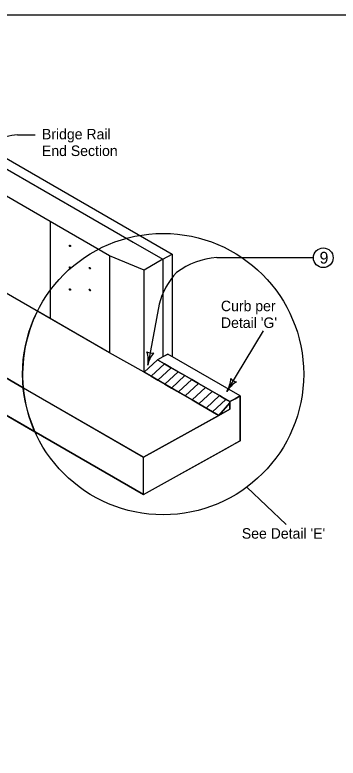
# Model space of a CAD drawing. Extents: x -2134934 to -2124557, y -2139046 to -2134021.
# Drawn here: x -2125788 to -2125295, y -2138168 to -2137036 of the extents above; entities that cross this region are included whole.
import ezdxf

# ---------------------------------------------------------------- set-up
doc = ezdxf.new("R2010")
doc.units = 0
for name, color, linetype in [('Barrier', 7, 'Continuous'), ('BridgeSuperStructureExisting', 7, 'Continuous'), ('dsnAlignmentStation', 7, 'Continuous'), ('dsnCellElements', 7, 'Continuous')]:
    doc.layers.add(name, color=color, linetype=linetype)

msp = doc.modelspace()

# ---------------------------------------------------------------- linework, layer by layer
at = {"layer": 'BridgeSuperStructureExisting'}
for p, q in [((-2126050, -2137110.4), (-2125548.2, -2137400.1)), ((-2125783.6, -2137218.5), (-2125756.7, -2137218.5)), ((-2125753.4, -2137487.2), (-2126112.2, -2137280.1)), ((-2125643.5, -2137550.7), (-2126112.2, -2137280.1)), ((-2125775, -2137603.9), (-2126226.3, -2137343.3)), ((-2126226.3, -2137343.3), (-2125775, -2137603.9)), ((-2125734, -2137350.5), (-2125734, -2137498.4)), ((-2126226.3, -2137400), (-2125757.2, -2137670.8)), ((-2125562.4, -2137408.2), (-2125548.2, -2137400.1)), ((-2125548.2, -2137400.1), (-2125548.2, -2137556.2)), ((-2125643.5, -2137402.8), (-2125643.5, -2137550.7)), ((-2125480.2, -2137405.5), (-2125332.7, -2137405.5)), ((-2125590.7, -2137580.2), (-2125590.7, -2137424.6)), ((-2126029.2, -2137457.2), (-2125591.9, -2137709.6)), ((-2125568, -2137476.6), (-2125585.2, -2137569.6)), ((-2125734, -2137498.4), (-2125753.4, -2137487.2)), ((-2125643.5, -2137550.7), (-2125734, -2137498.4)), ((-2126029.2, -2137513.8), (-2125591.9, -2137766.2)), ((-2125591.9, -2137766.2), (-2126029.2, -2137513.8)), ((-2125464.8, -2137609.5), (-2125408.7, -2137517.1)), ((-2125590.7, -2137580.2), (-2125643.5, -2137550.7)), ((-2125590.7, -2137580.2), (-2125643.5, -2137550.7)), ((-2125562.4, -2137556.9), (-2125570.2, -2137561.3)), ((-2125444.3, -2137616.2), (-2125554.5, -2137552.6)), ((-2125444.3, -2137616.2), (-2125554.5, -2137552.6)), ((-2125570.2, -2137561.3), (-2125590.7, -2137580.2)), ((-2125570.2, -2137561.3), (-2125590.7, -2137580.2)), ((-2125580.2, -2137586.3), (-2125559.8, -2137567.3)), ((-2125559.8, -2137567.3), (-2125580.2, -2137586.3)), ((-2125559.8, -2137567.3), (-2125580.2, -2137586.3)), ((-2125559.8, -2137567.3), (-2125570.2, -2137561.3)), ((-2125570.2, -2137561.3), (-2125559.8, -2137567.3)), ((-2125460, -2137624.9), (-2125570.2, -2137561.3)), ((-2125549.4, -2137573.3), (-2125559.8, -2137567.3)), ((-2125559.8, -2137567.3), (-2125549.4, -2137573.3)), ((-2125580.2, -2137586.3), (-2125590.7, -2137580.2)), ((-2125590.7, -2137580.2), (-2125580.2, -2137586.3)), ((-2125480.5, -2137643.9), (-2125590.7, -2137580.2)), ((-2125476.9, -2137645.9), (-2125590.7, -2137580.2)), ((-2125569.8, -2137592.3), (-2125549.4, -2137573.3)), ((-2125549.4, -2137573.3), (-2125569.8, -2137592.3)), ((-2125549.4, -2137573.3), (-2125569.8, -2137592.3)), ((-2125559.4, -2137598.3), (-2125539, -2137579.3)), ((-2125539, -2137579.3), (-2125559.4, -2137598.3)), ((-2125539, -2137579.3), (-2125559.4, -2137598.3)), ((-2125539, -2137579.3), (-2125549.4, -2137573.3)), ((-2125549.4, -2137573.3), (-2125539, -2137579.3)), ((-2125528.6, -2137585.3), (-2125539, -2137579.3)), ((-2125539, -2137579.3), (-2125528.6, -2137585.3)), ((-2125580.2, -2137586.3), (-2125569.8, -2137592.3)), ((-2125569.8, -2137592.3), (-2125559.4, -2137598.3)), ((-2125549, -2137604.3), (-2125528.6, -2137585.3)), ((-2125528.6, -2137585.3), (-2125549, -2137604.3)), ((-2125528.6, -2137585.3), (-2125549, -2137604.3)), ((-2125518.3, -2137591.3), (-2125538.4, -2137609.9)), ((-2125775, -2137603.9), (-2125591.9, -2137709.6)), ((-2125591.9, -2137709.6), (-2125775, -2137603.9)), ((-2125559.4, -2137598.3), (-2125549, -2137604.3)), ((-2125549, -2137604.3), (-2125528.2, -2137616.3)), ((-2125528.2, -2137616.3), (-2125507.8, -2137597.3)), ((-2125507.8, -2137597.3), (-2125528.2, -2137616.3)), ((-2125507.8, -2137597.3), (-2125528.2, -2137616.3)), ((-2125517.8, -2137622.3), (-2125497.4, -2137603.3)), ((-2125497.4, -2137603.3), (-2125517.8, -2137622.3)), ((-2125497.4, -2137603.3), (-2125517.8, -2137622.3)), ((-2125497.4, -2137603.3), (-2125507.8, -2137597.3)), ((-2125507.8, -2137597.3), (-2125497.4, -2137603.3)), ((-2125486.9, -2137609.4), (-2125507.3, -2137628.4)), ((-2125475.9, -2137615.7), (-2125496.3, -2137634.7)), ((-2125528.2, -2137616.3), (-2125517.8, -2137622.3)), ((-2125517.8, -2137622.3), (-2125507.3, -2137628.4)), ((-2125486.6, -2137640.3), (-2125466.2, -2137621.4)), ((-2125466.2, -2137621.4), (-2125486.6, -2137640.3)), ((-2125466.2, -2137621.4), (-2125486.6, -2137640.3)), ((-2125476.9, -2137645.9), (-2125460, -2137626.8)), ((-2125460, -2137626.8), (-2125476.9, -2137645.9)), ((-2125476.9, -2137645.9), (-2125460, -2137626.8)), ((-2125460, -2137624.9), (-2125466.2, -2137621.4)), ((-2125466.2, -2137621.4), (-2125460, -2137624.9)), ((-2125452.2, -2137620.6), (-2125460, -2137624.9)), ((-2125460, -2137624.9), (-2125452.2, -2137620.6)), ((-2125452.2, -2137620.6), (-2125460, -2137624.9)), ((-2125460, -2137626.8), (-2125460, -2137624.9)), ((-2125460, -2137636.6), (-2125460, -2137624.9)), ((-2125460, -2137636.6), (-2125460, -2137626.8)), ((-2125444.3, -2137616.2), (-2125452.2, -2137620.6)), ((-2125452.2, -2137620.6), (-2125444.3, -2137616.2)), ((-2125444.3, -2137616.2), (-2125452.2, -2137620.6)), ((-2125444.3, -2137684.5), (-2125444.3, -2137616.2)), ((-2125591.9, -2137709.6), (-2125460, -2137636.6)), ((-2125507.3, -2137628.4), (-2125486.6, -2137640.3)), ((-2125460, -2137636.6), (-2125476.9, -2137645.9)), ((-2125476.9, -2137645.9), (-2125460, -2137636.6)), ((-2125591.9, -2137709.6), (-2125476.9, -2137645.9)), ((-2125476.9, -2137645.9), (-2125591.9, -2137709.6)), ((-2125486.6, -2137640.3), (-2125480.5, -2137643.9)), ((-2125476.9, -2137645.9), (-2125480.5, -2137643.9)), ((-2125480.5, -2137643.9), (-2125476.9, -2137645.9)), ((-2125757.2, -2137670.8), (-2125591.9, -2137766.2)), ((-2125487.5, -2137708.4), (-2125452.2, -2137688.8)), ((-2125467.3, -2137697.2), (-2125452.2, -2137688.8)), ((-2125452.2, -2137688.8), (-2125444.3, -2137684.5)), ((-2125444.3, -2137684.5), (-2125452.2, -2137688.8)), ((-2125591.9, -2137766.2), (-2125467.3, -2137697.2)), ((-2125591.9, -2137766.2), (-2125591.9, -2137709.6)), ((-2125434.4, -2137755.2), (-2125374.1, -2137812))]:
    msp.add_line(p, q, dxfattribs=at)
for points in [[(-2126064.2, -2137118.5), (-2125698.1, -2137329.8), (-2125607.6, -2137382.1), (-2125562.4, -2137408.2), (-2125590.7, -2137424.6), (-2125643.5, -2137402.8), (-2125734, -2137350.5), (-2125915, -2137246), (-2126100, -2137139.2)], [(-2125562.4, -2137408.2), (-2125562.4, -2137556.9)], [(-2125590.7, -2137580.2), (-2125643.5, -2137550.7)], [(-2125562.4, -2137556.9), (-2125570.2, -2137561.3)], [(-2125554.5, -2137552.6), (-2125555.3, -2137553), (-2125562.4, -2137556.9)], [(-2125554.5, -2137552.6), (-2125562.4, -2137556.9)], [(-2125555.3, -2137553), (-2125562.4, -2137556.9)], [(-2125559.4, -2137598.3), (-2125569.8, -2137592.3), (-2125580.2, -2137586.3)], [(-2125507.8, -2137597.3), (-2125518.3, -2137591.3), (-2125528.6, -2137585.3)], [(-2125528.6, -2137585.3), (-2125518.3, -2137591.3), (-2125507.8, -2137597.3)], [(-2125528.2, -2137616.3), (-2125549, -2137604.3), (-2125559.4, -2137598.3)], [(-2125466.2, -2137621.4), (-2125475.9, -2137615.8), (-2125497.4, -2137603.3)], [(-2125497.4, -2137603.3), (-2125475.9, -2137615.8), (-2125466.2, -2137621.4)], [(-2125480.5, -2137643.9), (-2125486.6, -2137640.3), (-2125507.3, -2137628.4), (-2125517.8, -2137622.3), (-2125528.2, -2137616.3)], [(-2125460, -2137624.9), (-2125460, -2137626.8), (-2125460, -2137636.6)], [(-2125444.3, -2137616.2), (-2125444.3, -2137684.5)], [(-2125591.9, -2137766.2), (-2125487.5, -2137708.4), (-2125467.3, -2137697.2)]]:
    msp.add_lwpolyline(points, dxfattribs=at)
for centre, radius in [((-2125561.8, -2137583), 214.2), ((-2125317.8, -2137405.8), 15)]:
    msp.add_circle(centre, radius, dxfattribs=at)
for centre, radius, start, end in [((-2125775.9, -2137309.2), 91, 94.8409, 140.1467), ((-2125471.3, -2137522.6), 117.5, 94.3399, 126.627), ((-2125454.7, -2137507.5), 117.5, 137.5971, 164.7195), ((-2125561.8, -2137583), 214.2, 153.4358, 185.6063), ((-2125561.8, -2137583), 214.2, 153.4358, 185.6063), ((-2125561.8, -2137583), 214.2, 185.6063, 204.2018), ((-2125561.8, -2137583), 214.2, 185.6063, 204.2018)]:
    msp.add_arc(centre, radius, start, end, dxfattribs=at)
for centre in [(-2125703.8, -2137387.7), (-2125703.8, -2137420.9), (-2125673.6, -2137421.7), (-2125703.8, -2137454.1), (-2125673.6, -2137454.9)]:
    msp.add_ellipse(centre, major_axis=(0.67, -1.15), ratio=0.57735, dxfattribs=at)
at = {"layer": 'dsnAlignmentStation'}
msp.add_lwpolyline([(-2127734.4, -2137035.9), (-2124599.4, -2137035.9), (-2124599.4, -2139045.9), (-2127734.4, -2139045.9)], close=True, dxfattribs=at)
at = {"layer": 'dsnCellElements'}
for centre, radius, start, end in [((-2125578.7, -2137534.5), 16.4, 241.782, 277.2487), ((-2125627, -2137561.8), 42.5, 349.5153, 17.5878), ((-2125543.4, -2137577.3), 42.5, 141.4428, 169.5153), ((-2125501.1, -2137587.4), 42.5, 328.7108, 356.7833), ((-2125446.3, -2137579), 16.4, 220.9775, 256.4442), ((-2125428.5, -2137631.5), 42.5, 120.6383, 148.7108)]:
    msp.add_arc(centre, radius, start, end, dxfattribs=at)

# ---------------------------------------------------------------- texts
at = {"layer": 'Barrier'}
msp.add_text('9', height=18, dxfattribs=at).set_placement((-2125323.4, -2137414.8))
at = {"layer": 'BridgeSuperStructureExisting'}
for s, p in [('Bridge Rail ', (-2125746.5, -2137225.5)), ('End Section', (-2125746.5, -2137250.9)), ('Curb per', (-2125473.7, -2137487.2)), ("Detail 'G'", (-2125473.7, -2137512.7)), ("See Detail 'E'", (-2125441.9, -2137833.6))]:
    msp.add_text(s, height=16, dxfattribs=at).set_placement(p)

doc.saveas('drawing.dxf')
